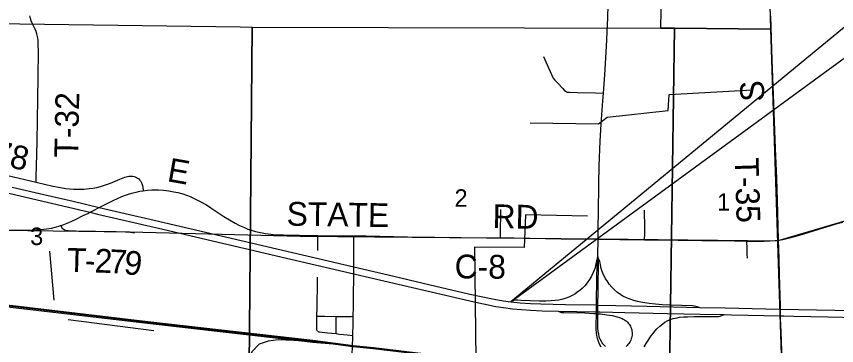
# Model space of a CAD drawing. Extents: x 0 to 34, y 0 to 22.
# Drawn here: x 5.024 to 6.003, y 18.052 to 18.445 of the extents above; entities that cross this region are included whole.
import ezdxf

# ---------------------------------------------------------------- set-up
doc = ezdxf.new("R2010")
doc.units = 0
for name, color, linetype in [('GM_X_Corporation', 7, 'Continuous'), ('GM_X_County_Road', 7, 'Continuous'), ('GM_X_County_Road_Text', 7, 'Continuous'), ('GM_X_Interchange_Ramps', 7, 'Continuous'), ('GM_X_Minor_River', 7, 'Continuous'), ('GM_X_Rail_Line', 7, 'Continuous'), ('GM_X_Section_Text', 7, 'Continuous'), ('GM_X_State_Route', 7, 'Continuous'), ('GM_X_Township_Road', 7, 'Continuous'), ('GM_X_Township_Road_Text', 7, 'Continuous'), ('SH_Text', 7, 'Continuous')]:
    doc.layers.add(name, color=color, linetype=linetype)

msp = doc.modelspace()

# ---------------------------------------------------------------- linework, layer by layer
at = {"layer": 'GM_X_Corporation'}
for points in [[(5.90965, 18.93457), (5.92403, 18.42993), (5.8093, 18.4313), (5.79308, 18.4314), (5.80232, 18.93473)], [(5.2907, 18.43288), (5.30482, 18.43261), (5.30041, 17.93698), (5.29864, 17.93686), (4.7909, 17.94084), (4.79371, 18.43949)], [(5.8093, 18.4313), (5.80201, 17.93395), (5.30041, 17.93698), (5.30482, 18.43261), (5.79308, 18.4314)], [(5.92403, 18.42993), (5.94033, 17.931), (5.80201, 17.93395), (5.8093, 18.4313)]]:
    msp.add_lwpolyline(points, close=True, dxfattribs=at)
msp.add_lwpolyline([(5.92381, 18.44573), (5.92558, 18.39292), (5.92626, 18.37274), (5.92865, 18.30907), (5.92948, 18.28734), (5.93094, 18.25163), (5.93171, 18.22523), (5.93292, 18.17807), (5.93362, 18.15534), (5.93423, 18.1367), (5.93532, 18.09944), (5.93536, 18.09573), (5.93545, 18.08777), (5.93548, 18.08422), (5.93634, 18.06829), (5.93745, 18.03423)], dxfattribs=at)
at = {"layer": 'GM_X_County_Road'}
for points in [[(5.07632, 18.19516), (5.07826, 18.19583), (5.0859, 18.19874), (5.08953, 18.20037), (5.09408, 18.20255), (5.10319, 18.20713), (5.10862, 18.20986), (5.11131, 18.21122), (5.11457, 18.21285), (5.1225, 18.21686), (5.13171, 18.22152), (5.139, 18.22509), (5.14937, 18.22983), (5.15481, 18.23196), (5.15849, 18.23313), (5.16293, 18.23437), (5.16651, 18.23525), (5.17078, 18.23621), (5.17481, 18.23694)], [(5.17481, 18.23694), (5.18009, 18.23759), (5.18518, 18.23792), (5.19298, 18.23784), (5.19921, 18.23748), (5.20542, 18.23678), (5.21158, 18.23574), (5.21616, 18.23475), (5.22219, 18.23311), (5.22664, 18.23162), (5.231, 18.22991), (5.2367, 18.22735), (5.24364, 18.22379), (5.25041, 18.21992), (5.25569, 18.2166), (5.2712, 18.20622), (5.2778, 18.20213), (5.28453, 18.19827), (5.29003, 18.19542), (5.29567, 18.19283), (5.29998, 18.1911), (5.30437, 18.18959), (5.30882, 18.1883), (5.31486, 18.18687), (5.32094, 18.18569), (5.32708, 18.18485), (5.33326, 18.18435), (5.34257, 18.18403), (5.36123, 18.18383), (5.37678, 18.18352), (5.3835, 18.18344)], [(4.93963, 18.19125), (4.9504, 18.19123), (4.96792, 18.19092), (5.00338, 18.19044), (5.0252, 18.18995), (5.04077, 18.18989), (5.04699, 18.19005), (5.05318, 18.19048), (5.05934, 18.19122), (5.06545, 18.19231), (5.0715, 18.19369), (5.07411, 18.19441), (5.07632, 18.19516)], [(5.93303, 18.17779), (5.93554, 18.17821), (5.93858, 18.1788), (5.94485, 18.18026), (5.95124, 18.18197), (5.96361, 18.18543), (5.99181, 18.19414), (6.00506, 18.19796), (6.01002, 18.19933)], [(5.3835, 18.18344), (5.40945, 18.18314), (5.42188, 18.183), (5.42654, 18.18297)], [(5.42559, 18.08676), (5.42582, 18.09817), (5.42594, 18.11216), (5.42624, 18.13378), (5.42624, 18.13749), (5.42625, 18.14589), (5.42627, 18.15714), (5.42642, 18.16645), (5.42653, 18.18175), (5.42654, 18.18297)], [(5.42654, 18.18297), (5.44056, 18.18286), (5.49032, 18.18191), (5.58675, 18.18077), (5.60165, 18.18062)], [(5.60165, 18.18062), (5.61787, 18.18046), (5.67385, 18.17959), (5.69563, 18.17946), (5.70341, 18.17931), (5.7174, 18.179), (5.7181, 18.179)], [(5.7181, 18.179), (5.74384, 18.17868), (5.76561, 18.17845), (5.77334, 18.17831)], [(5.77334, 18.17831), (5.81359, 18.17778), (5.84223, 18.17746), (5.88079, 18.17692), (5.89576, 18.17675)], [(5.89576, 18.17675), (5.90703, 18.17654), (5.91623, 18.1766), (5.9235, 18.17691), (5.92927, 18.17737), (5.93303, 18.17779)], [(5.42506, 18.06395), (5.42542, 18.078), (5.42559, 18.08676)], [(5.42457, 18.04327), (5.42467, 18.0485), (5.42506, 18.06395)]]:
    msp.add_lwpolyline(points, dxfattribs=at)
at = {"layer": 'GM_X_Interchange_Ramps'}
for points in [[(5.71715, 18.15539), (5.71619, 18.15347), (5.71565, 18.15095), (5.7151, 18.14788), (5.71437, 18.14485), (5.71343, 18.14187), (5.7123, 18.13897), (5.71025, 18.13477), (5.70783, 18.13075), (5.70513, 18.12693), (5.70214, 18.12332), (5.69885, 18.12), (5.69649, 18.11795), (5.69276, 18.11512), (5.69016, 18.1134), (5.68607, 18.11112), (5.68324, 18.1098), (5.67888, 18.10813), (5.67437, 18.10689), (5.67132, 18.10625), (5.66669, 18.10558), (5.66203, 18.10518), (5.65579, 18.10493), (5.64798, 18.10488), (5.63705, 18.10517), (5.62615, 18.10575), (5.62215, 18.10606), (5.62027, 18.10609), (5.61749, 18.1056), (5.61399, 18.10416)], [(5.83923, 18.09738), (5.83333, 18.09898), (5.83083, 18.09928), (5.80522, 18.09995), (5.79435, 18.10053), (5.78661, 18.1012), (5.77889, 18.10214), (5.7712, 18.10334), (5.76511, 18.10458), (5.76059, 18.10574), (5.75615, 18.10716), (5.75182, 18.10891), (5.74766, 18.11101), (5.745, 18.11261), (5.7412, 18.11531), (5.73766, 18.11833), (5.73438, 18.12165), (5.73136, 18.12521), (5.72864, 18.129), (5.72701, 18.13164), (5.72553, 18.13438), (5.72422, 18.1372), (5.72258, 18.14156), (5.72186, 18.14393), (5.72139, 18.14603), (5.72089, 18.14832), (5.72037, 18.15066), (5.72004, 18.15212), (5.7197, 18.15366), (5.71929, 18.1544), (5.71865, 18.15555)], [(5.77292, 18.05037), (5.77555, 18.05421), (5.78152, 18.06333), (5.7833, 18.06587), (5.7862, 18.06952), (5.78828, 18.07183), (5.79162, 18.07505), (5.79528, 18.07795), (5.79787, 18.07965), (5.80057, 18.08118), (5.80337, 18.08248), (5.80774, 18.08407), (5.81226, 18.08514), (5.81532, 18.08563), (5.81996, 18.08608), (5.82461, 18.08626), (5.83238, 18.08637), (5.86177, 18.08635), (5.86374, 18.08676), (5.86847, 18.08886)], [(5.71758, 18.05874), (5.71845, 18.05602), (5.71966, 18.05317), (5.72113, 18.05043)]]:
    msp.add_lwpolyline(points, dxfattribs=at)
at = {"layer": 'GM_X_Minor_River'}
for points in [[(5.63702, 18.318), (5.71846, 18.31686), (5.72867, 18.32489), (5.80153, 18.33264), (5.80295, 18.35185), (5.9022, 18.35763)], [(5.70535, 18.20639), (5.63131, 18.20794), (5.6298, 18.16897), (5.57057, 18.16946), (5.57221, 18.03472), (5.61329, 17.94388), (5.58893, 17.9183)], [(5.06298, 18.16481), (5.06822, 18.10621)], [(5.08542, 18.08281), (5.18761, 18.06979)]]:
    msp.add_lwpolyline(points, dxfattribs=at)
at = {"layer": 'GM_X_Rail_Line'}
for points in [[(4.40206, 18.19809), (4.68917, 18.19409), (5.00635, 18.18976), (5.15875, 18.1876), (5.36248, 18.18265), (5.7183, 18.17956), (5.93191, 18.17708), (6.25187, 18.2714), (6.49949, 18.34686), (7.04327, 18.51787), (7.07913, 18.52777), (7.1289, 18.52993), (7.24173, 18.53643), (7.28965, 18.56333), (7.33819, 18.59766)], [(4.30105, 18.18289), (4.6693, 18.13987), (5.18031, 18.07961), (5.37736, 18.0572), (5.42538, 18.05081), (5.44961, 18.04815), (5.5891, 18.03157), (5.69016, 18.01975), (5.75885, 18.01162), (5.88732, 17.99663), (5.93939, 17.9904), (5.98013, 17.9856), (5.99952, 17.98326), (6.01725, 17.98072)], [(4.30119, 18.18404), (4.66944, 18.14103), (5.18045, 18.08076), (5.3775, 18.05835), (5.42552, 18.05196), (5.44974, 18.0493), (5.58924, 18.03272), (5.6903, 18.0209), (5.75899, 18.01277), (5.88746, 17.99778), (5.93953, 17.99155), (5.98027, 17.98676), (5.99967, 17.98441), (6.01742, 17.98187)], [(4.96457, 18.10387), (5.18018, 18.07845), (5.36394, 18.05756)], [(5.36394, 18.05756), (5.33588, 18.05882), (5.32393, 18.05721), (5.31346, 18.05356), (5.3051, 18.04484), (5.30025, 18.03583), (5.29714, 18.02192)], [(5.36394, 18.05756), (5.37722, 18.05605), (5.40163, 18.05397)]]:
    msp.add_lwpolyline(points, dxfattribs=at)
at = {"layer": 'GM_X_State_Route'}
for p, q in [((5.67047, 18.09307), (5.71495, 18.09214)), ((5.71767, 18.08015), (5.7177, 18.08976)), ((5.72018, 18.09203), (5.73512, 18.09172)), ((5.73512, 18.09172), (5.75006, 18.0914))]:
    msp.add_line(p, q, dxfattribs=at)
for points in [[(5.72433, 18.35357), (5.7259, 18.37529), (5.72805, 18.40943), (5.72945, 18.44362), (5.73005, 18.45916), (5.7308, 18.48091), (5.7338, 18.56482), (5.73462, 18.5819), (5.73568, 18.60987), (5.73689, 18.63783), (5.73697, 18.64026)], [(5.7181, 18.179), (5.7182, 18.18585), (5.71822, 18.19363), (5.71839, 18.21072), (5.71875, 18.24493), (5.71928, 18.26668), (5.72048, 18.29619), (5.72164, 18.31636), (5.72365, 18.34427), (5.72433, 18.35357)], [(4.7487, 18.29602), (4.78302, 18.28797), (4.82996, 18.2771), (4.91164, 18.2578), (4.97673, 18.24265), (5.11131, 18.21122), (5.12052, 18.20908), (5.19314, 18.19203), (5.346, 18.15629), (5.42624, 18.13749), (5.4398, 18.13432), (5.56992, 18.1039), (5.58663, 18.10033), (5.59579, 18.09862), (5.60499, 18.09719), (5.61577, 18.09583), (5.62658, 18.09478), (5.63742, 18.09404), (5.65139, 18.0935), (5.67047, 18.09307)], [(5.0184, 18.24124), (5.05625, 18.23237), (5.0911, 18.22425), (5.1225, 18.21686), (5.12743, 18.2157), (5.15319, 18.20974), (5.18801, 18.20155), (5.42625, 18.14589), (5.47423, 18.13468), (5.50902, 18.12645), (5.56505, 18.11335), (5.58024, 18.10996), (5.59397, 18.10721), (5.60473, 18.1054), (5.61399, 18.10416), (5.62483, 18.10307), (5.63726, 18.10214), (5.6497, 18.10158), (5.67925, 18.10093), (5.71607, 18.10031), (5.7177, 18.10029), (5.73921, 18.09955), (5.77654, 18.09874), (5.83923, 18.09738)], [(5.7177, 18.09), (5.7177, 18.09076), (5.7177, 18.09209), (5.7177, 18.10029), (5.71805, 18.11663), (5.71865, 18.15555), (5.71787, 18.15961), (5.7181, 18.179)], [(5.71758, 18.05874), (5.71678, 18.06199), (5.71607, 18.0666), (5.71573, 18.07124), (5.71564, 18.0759), (5.71592, 18.09), (5.71595, 18.09212), (5.716, 18.09453), (5.71607, 18.10031), (5.71659, 18.13488), (5.71715, 18.15539), (5.71787, 18.15961)], [(5.83923, 18.09738), (5.86987, 18.09672), (5.9181, 18.09579), (5.93547, 18.09545)], [(5.67047, 18.09307), (5.67407, 18.09146), (5.67545, 18.09122), (5.67719, 18.09122), (5.70221, 18.09075), (5.7131, 18.0902), (5.71592, 18.09), (5.7177, 18.08988), (5.72086, 18.08956), (5.72858, 18.08865), (5.73468, 18.08756), (5.74076, 18.08627), (5.74375, 18.0854), (5.74664, 18.08424), (5.74802, 18.08354), (5.74935, 18.08275), (5.75063, 18.08188), (5.75183, 18.08089), (5.75296, 18.07983), (5.75401, 18.07868), (5.75496, 18.07745), (5.75581, 18.07616), (5.75657, 18.0748), (5.7572, 18.07338), (5.75773, 18.07192), (5.75813, 18.07042), (5.75841, 18.0689), (5.75856, 18.06735), (5.75859, 18.0658), (5.75849, 18.06425), (5.75828, 18.06271), (5.75794, 18.06119), (5.75749, 18.0597), (5.75693, 18.05825), (5.75625, 18.05685), (5.75547, 18.0555), (5.7546, 18.05422), (5.75363, 18.05301), (5.75255, 18.05188), (5.7514, 18.05084)], [(5.71495, 18.09214), (5.71595, 18.09212), (5.7177, 18.09209), (5.72018, 18.09203)], [(5.75006, 18.0914), (5.80084, 18.09032), (5.83975, 18.08944), (5.86847, 18.08886)], [(5.86847, 18.08886), (5.87711, 18.08868), (5.93556, 18.0875), (5.93962, 18.0874)], [(5.93547, 18.09545), (6.00054, 18.09408), (6.04409, 18.09308)], [(5.93962, 18.0874), (5.95182, 18.08713), (5.99229, 18.08627), (6.04521, 18.08512), (6.05144, 18.08498), (6.067, 18.0844), (6.07634, 18.08377), (6.08565, 18.08279), (6.09491, 18.08145), (6.10258, 18.08008), (6.11174, 18.07817), (6.12083, 18.07595), (6.12983, 18.07337), (6.13873, 18.07046), (6.1475, 18.06721), (6.15615, 18.06364), (6.16466, 18.05975), (6.17303, 18.05555), (6.18125, 18.05108), (6.18802, 18.04706)], [(5.72696, 18.05075), (5.72579, 18.05175), (5.72467, 18.05284), (5.72366, 18.054), (5.72273, 18.05525), (5.7219, 18.05655), (5.7205, 18.05932), (5.72025, 18.06002), (5.71946, 18.06223), (5.71871, 18.06525), (5.71822, 18.06832), (5.7178, 18.07297), (5.71766, 18.07763), (5.71767, 18.08015)]]:
    msp.add_lwpolyline(points, dxfattribs=at)
at = {"layer": 'GM_X_Township_Road'}
msp.add_line((5.38228, 18.07403), (5.38239, 18.08691), dxfattribs=at)
for points in [[(5.93303, 18.17779), (5.93182, 18.22495), (5.93105, 18.25135), (5.92959, 18.28706), (5.92876, 18.30879), (5.92637, 18.37246), (5.92569, 18.39264), (5.92393, 18.44545), (5.92261, 18.48116), (5.92007, 18.55881), (5.91828, 18.60384), (5.91687, 18.64733), (5.91564, 18.69081), (5.91464, 18.72809), (5.91288, 18.79799), (5.91225, 18.81818), (5.912, 18.82597)], [(5.04692, 18.2472), (5.04714, 18.25372), (5.04756, 18.26614), (5.04843, 18.29566), (5.04918, 18.34695), (5.04946, 18.37337), (5.04978, 18.4029), (5.04964, 18.41221), (5.04932, 18.41683), (5.0487, 18.42141), (5.04803, 18.4244), (5.04707, 18.42731), (5.04585, 18.43012), (5.04311, 18.43571), (5.04128, 18.44003), (5.04025, 18.44299), (5.03946, 18.44604)], [(5.65293, 18.39726), (5.65733, 18.38726), (5.66226, 18.37579), (5.66368, 18.37302), (5.66448, 18.37168), (5.66635, 18.3692), (5.66955, 18.36578), (5.67602, 18.35901), (5.67767, 18.35713), (5.67926, 18.35576), (5.6801, 18.35521), (5.68103, 18.3549), (5.68218, 18.35479), (5.68371, 18.35476), (5.69322, 18.35449), (5.71505, 18.35384), (5.72433, 18.35357)], [(4.89508, 18.28258), (4.9504, 18.26977), (5.00648, 18.25662), (5.04692, 18.2472)], [(5.04692, 18.2472), (5.06712, 18.2425), (5.07625, 18.2406), (5.08237, 18.23959), (5.08699, 18.23906), (5.09162, 18.23875), (5.09782, 18.23867), (5.10402, 18.23893), (5.1102, 18.23948), (5.11481, 18.2401), (5.11937, 18.24096), (5.12388, 18.24207), (5.1298, 18.24389), (5.13565, 18.24599), (5.14717, 18.25068), (5.15301, 18.25299), (5.15604, 18.2539), (5.1576, 18.25422), (5.15918, 18.25443), (5.16078, 18.25447), (5.16236, 18.25436), (5.16394, 18.25403), (5.16546, 18.25354), (5.16692, 18.25283), (5.16828, 18.25197), (5.16953, 18.25096), (5.17066, 18.24981), (5.17165, 18.24855), (5.17249, 18.24718), (5.17319, 18.24572), (5.17374, 18.24422), (5.17403, 18.24314), (5.17432, 18.24135), (5.17481, 18.23694)], [(5.60165, 18.18062), (5.60156, 18.1876), (5.60152, 18.19072), (5.60171, 18.20793), (5.60171, 18.2144)], [(5.77334, 18.17831), (5.7734, 18.17979), (5.77362, 18.18431), (5.77375, 18.1921), (5.77359, 18.21353)], [(5.07632, 18.19516), (5.07654, 18.19483), (5.07819, 18.19233), (5.07919, 18.19126), (5.08033, 18.19048), (5.08155, 18.18984), (5.08333, 18.18934), (5.08524, 18.18928), (5.08832, 18.18899), (5.09454, 18.18879), (5.11785, 18.18847), (5.14271, 18.18805), (5.15358, 18.18786), (5.15979, 18.1875), (5.1646, 18.18673)], [(5.38332, 18.16558), (5.38344, 18.1731), (5.38357, 18.17823), (5.38356, 18.18118), (5.3835, 18.18344)], [(5.8962, 18.15632), (5.89598, 18.16113), (5.89579, 18.16734), (5.89576, 18.17675)], [(5.93881, 17.99987), (5.93849, 18.00757), (5.93756, 18.03396), (5.93645, 18.06801), (5.93559, 18.08394), (5.93556, 18.0875), (5.93547, 18.09545), (5.93543, 18.09916), (5.93434, 18.13642), (5.93373, 18.15506), (5.93303, 18.17779)], [(5.38239, 18.08691), (5.38249, 18.09772), (5.38298, 18.12801), (5.38308, 18.13357)], [(5.38239, 18.08691), (5.38412, 18.08689), (5.39166, 18.0868), (5.40521, 18.08653)], [(5.40508, 18.06606), (5.40512, 18.06762), (5.40517, 18.06964), (5.40517, 18.07707), (5.40521, 18.08653)], [(5.40521, 18.08653), (5.42304, 18.08673), (5.42559, 18.08676)], [(5.38288, 18.06896), (5.38248, 18.06967), (5.3823, 18.07027), (5.38226, 18.07088), (5.38226, 18.07155), (5.38228, 18.07403)], [(5.38288, 18.06896), (5.38365, 18.06853), (5.38436, 18.0683), (5.38524, 18.06819), (5.39506, 18.06718), (5.40508, 18.06606)], [(5.40508, 18.06606), (5.4094, 18.06558), (5.41846, 18.06464), (5.42506, 18.06395)]]:
    msp.add_lwpolyline(points, dxfattribs=at)
at = {"layer": 'SH_Text'}
msp.add_lwpolyline([(5.61399, 18.10416), (9.32697, 20.82299), (9.32697, 21.16525)], close=True, dxfattribs=at)

# ---------------------------------------------------------------- texts
at = {"layer": 'GM_X_County_Road_Text'}
for s, height, rotation, p in [('E', 0.02841, 350.08536, (5.20249, 18.24841)), ('STATE', 0.028409, 359.15755, (5.34597, 18.19521)), ('RD', 0.028409, 359.01779, (5.59182, 18.19227)), ('C-8', 0.028409, 359.54102, (5.54664, 18.13218))]:
    msp.add_text(s, height=height, rotation=rotation, dxfattribs=at).set_placement(p)
at = {"layer": 'GM_X_Section_Text'}
for s, p in [('2', (5.54662, 18.21776)), ('1', (5.86016, 18.21302)), ('3', (5.03996, 18.17198))]:
    msp.add_text(s, height=0.02093, rotation=0.00001, dxfattribs=at).set_placement(p)
at = {"layer": 'GM_X_Township_Road_Text'}
for s, height, rotation, p in [('S', 0.02841, 92.48812, (5.9167, 18.34396)), ('T-32', 0.028409, 88.93803, (5.09717, 18.27628)), ('T-278', 0.028409, 346.88512, (4.93791, 18.28292)), ('T-35', 0.028409, 271.76846, (5.88109, 18.27623)), ('T', 0.02841, 358.40339, (5.08369, 18.14016)), ('2', 0.02841, 357.98041, (5.11654, 18.13923)), ('7', 0.02841, 356.88656, (5.13388, 18.13862)), ('9', 0.02841, 353.05378, (5.15086, 18.13771)), ('-', 0.02841, 358.32931, (5.10492, 18.13957))]:
    msp.add_text(s, height=height, rotation=rotation, dxfattribs=at).set_placement(p)

doc.saveas('drawing.dxf')
